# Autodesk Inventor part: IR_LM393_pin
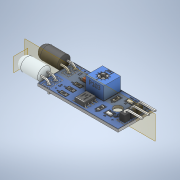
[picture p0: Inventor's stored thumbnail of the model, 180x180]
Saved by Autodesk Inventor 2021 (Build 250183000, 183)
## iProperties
Created: 2026-02
Part Number: IR_LM393_pin
Material: Generic
Document SubType Name: Modeling
Designer: alolo
Density: 1 g/cm^3
Appearance: Default
Sending System: Autodesk Inventor 2024
Preprocessor: ST-DEVELOPER v20
Title: IR_LM393_pin.stp
Author: quang
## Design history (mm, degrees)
feature "Solid1"
feature "Solid2:1"
feature "Solid2:2"
feature "Solid3:1"
feature "Solid3:2"
feature "Solid3:3"
feature "Solid3:4"
feature "Solid3:5"
feature "Solid3:6"
feature "Solid3:7"
feature "Solid4:1"
feature "Solid4:2"
feature "Solid4:3"
feature "Solid4:4"
feature "Solid4:5"
feature "Solid4:6"
feature "Solid4:7"
feature "Solid4:8"
feature "Solid4:9"
feature "Solid5:1"
feature "Solid5:2"
feature "Solid5:3"
feature "Solid6:1"
feature "Solid6:2"
feature "Solid6:3"
workplane "Work Plane2"
workplane "Work Plane3"
body "Solid2"
body "Solid3"
body "Solid4"
body "Solid5"
body "Solid6"
body "Solid7"
body "Solid8"
body "Solid9"
body "Solid10"
body "Solid11"
body "Solid12"
body "Solid13"
body "Solid14"
body "Solid15"
body "Solid16"
body "Solid17"
body "Solid18"
body "Solid19"
body "Solid20"
body "Solid21"
body "Solid22"
body "Solid23"
body "Solid24"
body "Solid25"
body "Solid26"
other parameters: "d0" = -9
